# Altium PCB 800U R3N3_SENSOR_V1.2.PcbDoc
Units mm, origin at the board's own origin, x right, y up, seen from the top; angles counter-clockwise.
Board outline 152.4 x 101.6 mm, 2 copper layers (Top Layer, Bottom Layer); 17 components, 10 nets, 29 pads, 17 vias.
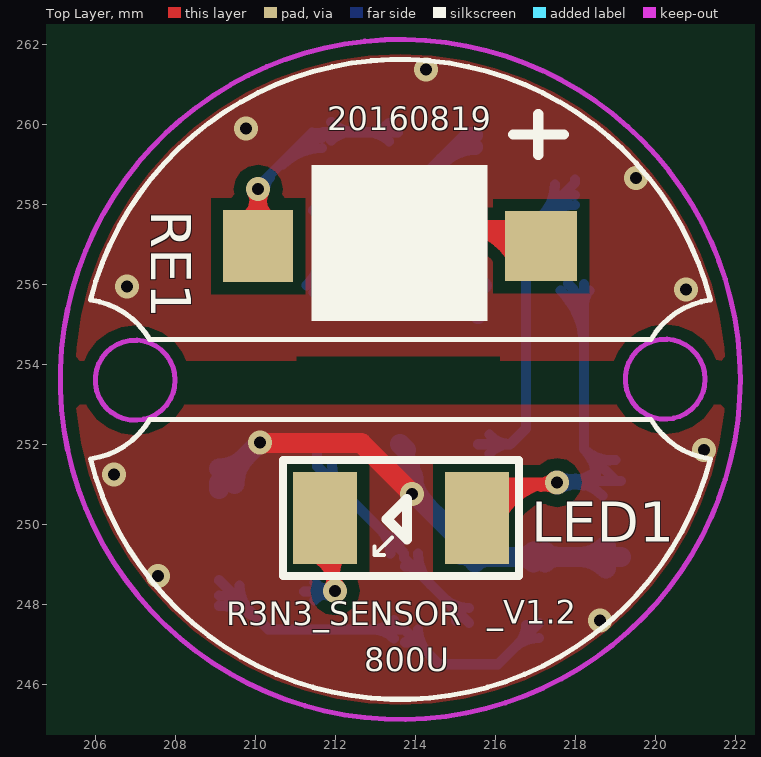
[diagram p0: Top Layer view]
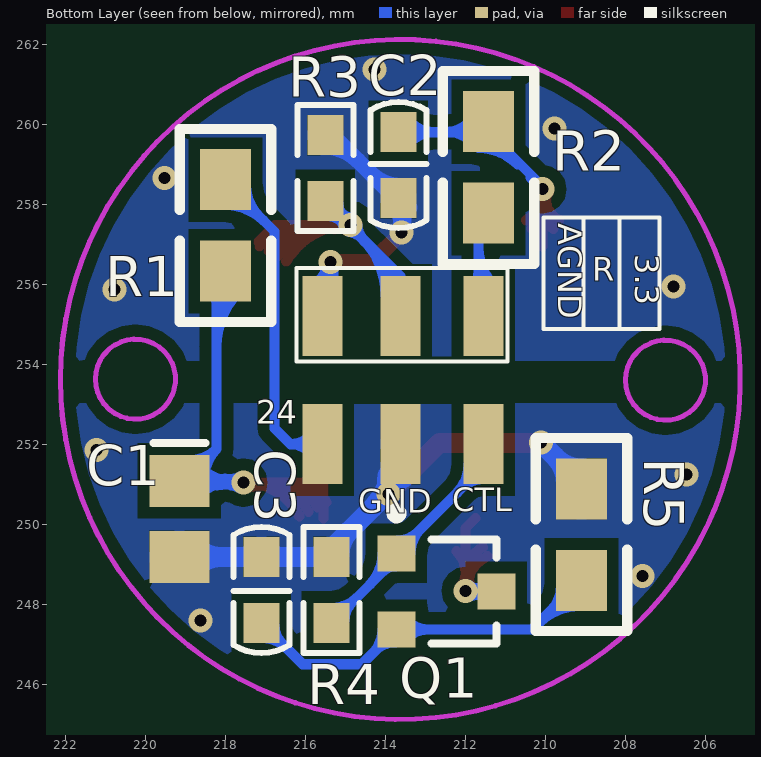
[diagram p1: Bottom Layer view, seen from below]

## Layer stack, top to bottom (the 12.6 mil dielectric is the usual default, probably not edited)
Top Layer: signal copper 0.0356
Dielectric: dielectric 0.32, FR-4, Dk 4.8
Bottom Layer: signal copper 0.0356

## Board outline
162.425,214.025 314.825,214.025 314.825,315.625 162.425,315.625

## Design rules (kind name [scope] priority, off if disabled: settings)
Clearance [All] p1: gap=0.3
PlaneConnect [Isvia] p1: planeconnectstyle=Relief reliefexpansion=0.508 reliefentries=4 reliefconductorwidth=0.254 reliefairgap=0.254
PolygonConnect [Isvia] p1: connectstyle=Direct reliefconductorwidth=0.254 reliefentries=4 polygonreliefangle="90 Angle" airgapwidth=0.254
RoutingVias [All] p1: holewidth=0.3 width=0.6 viastyle="Through Hole" minholewidth=0.3 minwidth=0.6 maxholewidth=0.3 maxwidth=0.6
SilkToSolderMaskClearance SilkscreenOverComponentPads [IsPad] p1: minsilkscreentomaskgap=0.254 clearancetoexposedcopper=TRUE
SolderMaskExpansion [All] p1: expansion=0.102
Width [All] p1: maxlimit=0.6 minlimit=0.254 preferedwidth=0.254 minimp=50.000000 maximp=50.000000 favimp=50.000000
26 further rules are at their usual default settings.

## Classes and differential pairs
component class "800U R3N3_TR": 3.3 24 C1 C2 C3 CTL GND LED1 Q1 R R1 R2 R3 R4 R5 RE1

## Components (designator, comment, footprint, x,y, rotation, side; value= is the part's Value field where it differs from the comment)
3.3 "" HOLE_SMD 211.55,255.21 r180 bottom (schematic designator 2)
24 "" HOLE_SMD 215.575,252 r180 bottom (schematic designator 1)
AGND "" HOLE_SMD 215.575,255.21 r180 bottom (schematic designator LEDCTL1)
C1 "105" C0805 219.15,250.13 r270 bottom
C2 "105" C0603 213.675,259.8 r270 bottom
C3 "102" C0603 217.1,247.53 r90 bottom
CTL "" HOLE_SMD 211.55,252 r180 bottom (schematic designator LEDCTL1)
GND "" HOLE_SMD 213.625,252 r180 bottom (schematic designator GND1)
LED1 "SIR67-21C" LED-3.5X2.8 213.65,250.15 r180 top locked
Q1 "MMBT5551" SOT-23 212.475,248.32 r270 bottom
R "" HOLE_SMD 213.625,255.21 r180 bottom (schematic designator LED_R1)
R1 "100" R0805 218,257.47 r90 bottom
R2 "100" R0805 211.425,258.92 r270 bottom
R3 "10K" R0603 215.5,259.725 r270 bottom
R4 "10K" R0603 215.35,249.18 r270 bottom
R5 "15" R0805 209.1,249.74 r270 bottom
RE1 "PD70-01C" LED9*4 213.65,256.95 r90 top locked

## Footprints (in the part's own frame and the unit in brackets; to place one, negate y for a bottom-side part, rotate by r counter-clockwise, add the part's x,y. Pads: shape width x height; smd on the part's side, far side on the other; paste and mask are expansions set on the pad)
C0603 [mm]
  rect 1x0.9 smd: 1(0,0) 2(1.65,0)
  silkscreen extent -0.75,-0.7 2.4,0.7
C0805 [mm] "Chip Capacitor; Body 2.0 x"
  rect 1.3x1.5 smd: 1(-0.95,0) 2(0.95,0)
  silkscreen extent -1.9,-0.65 -1.9,0.65
HOLE_SMD [mm]
  rect 1x2 smd: 1(0,0)
LED9*4 [mm]
  rect 1.75x1.8 smd: 1(0,-3.5)
  rect 1.8x1.75 smd: 2(0,3.575)
  silkscreen extent -1.87,-4.06 3.3,2.24
LED-3.5X2.8 [mm]
  rect 1.6x2.3 smd: 1(-1.9,0) 2(1.9,0)
  silkscreen extent -2.95,-1.45 2.95,1.45
R0603 [mm]
  rect 1x0.9 smd: 1(0,0) 2(1.65,0)
  silkscreen extent -0.75,-0.7 2.4,0.7
R0805 [mil]
  rect 60x50 smd: 1(-45,0) 2(45,0)
  silkscreen extent -95,-45 95,45
SOT-23 [mm] "SOT-23; 3 Leads; Body 3.0 x 2.6 mm"
  rect 0.9x0.95 smd: 1(-0.95,-1.25) 2(0.95,-1.25) 3(0,1.25)
  silkscreen extent -2.07,-1.38 1.3,1.25

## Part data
3.3 24 AGND CTL GND R: library part 焊
C1: library part Cap, "贴片电容"
C2 C3: library part Cap, "贴"
LED1: library part LED0, "贴"
Q1: library part NPN, "贴片NPN三极管"
R1 R2 R3 R4 R5: library part "Res Semi", "贴"
RE1: library part "Photo Sen", "贴"

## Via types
v1: diameter 0.6, hole 0.3, Top Layer to Bottom Layer, 17 vias

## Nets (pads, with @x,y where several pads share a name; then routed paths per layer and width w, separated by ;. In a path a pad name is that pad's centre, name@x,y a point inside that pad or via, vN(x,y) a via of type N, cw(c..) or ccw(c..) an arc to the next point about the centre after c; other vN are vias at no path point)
3.3V: 3.3.1 R2.2 | length 6
  Bottom Layer w0.254: 3.3.1@211.286,255.974 ccw(c210.348,256.912) 211.675,256.912 ; R2.2@211.447,257.847 cw(c210.895,257.295) 211.675,257.295 cw(c212.455,257.295) R2.2@211.903,257.847 ; 3.3.1@211.466,255.794 ccw(c210.961,256.299) 211.675,256.299 ; 211.675,256.309 ccw(c212.149,256.309) 3.3.1@211.814,255.974 ; R2.2@211.675,258.125 211.675,255.575 3.3.1@211.875,255.375
+24V: 24.1 R1.2 | length 11.8
  Bottom Layer w0.254: 24.1 216.375,252 ; 24.1@215.861,251.76 cw(c216.375,251.329) 216.375,252 ; 24.1@215.861,252.24 ccw(c216.375,252.671) 216.375,252 ; 217.041,257.581 cw(c218,256.621) R1.2@218,257.978 ; 217.171,257.711 ccw(c216.396,258.486) R1.2@217.492,258.486 ; R1.2@217.474,258.014 cw(c218,257.488) R1.2@218,258.232 ; R1.2 218,258.54 216.775,257.315 216.775,252.4 216.375,252
AGND: AGND.1 C2.2 R3.1 | length 11.4
  Top Layer w0.4: v1(213.6,257.29) 214.33,256.56 v1(215.375,256.56)
  Bottom Layer w0.4: C2.2@213.398,257.923 cw(c212.971,257.496) 213.575,257.496 cw(c214.179,257.496) C2.2@213.752,257.923 ; v1@213.513,257.34 ccw(c213.218,257.511) 213.548,257.599 ; 213.575,257.592 ccw(c213.902,257.592) v1@213.671,257.361 ; C2.2@213.575,258.15 C2.2@213.575,257.975 ; C2.2@213.575,258.45 ccw(c213.575,259.597) 214.386,258.786 ; v1(213.6,257.29) 213.575,257.315 C2.2@213.575,257.975 ; C2.2@213.621,257.668 ccw(c213.985,257.571) v1@213.681,257.349 ; 214.689,259.089 cw(c215.5,258.278) R3.1@215.5,259.425 ; R3.1 215.325,259.725 C2.2@213.575,257.975 ; AGND.1 215.375,255.41 v1(215.375,256.56) ccw(c216.047,256.56) AGND.1@215.721,255.972
  other v1: 220.775,255.87 206.8,255.94 219.525,258.65 209.775,259.89 214.275,261.37
GND: C1.2 C3.2 GND.1 R4.1 R5.1 | length 20.9
  Top Layer w0.5: v1@210.105,252.03 212.655,252.03 v1(213.925,250.76)
  Bottom Layer w0.5: R5.1 209.1,251.025 v1(210.115,252.04) ; R5.1@209.1,251.395 ccw(c209.1,252.288) 209.732,251.657 ; R5.1@209.485,251.01 cw(c210.451,251.01) 209.768,251.693 ; GND.1 GND.1@213.775,251.85 ; GND.1@213.7,251.3 213.55,251.15 213.585,251.15 215.35,249.385 R4.1 C3.2 C1.2 ; GND.1@213.875,251.5 ccw(c215.42,251.5) 214.328,250.407 ; v1@213.882,250.786 ccw(c213.398,251.077) GND.1@213.946,251.213 ; v1@213.918,250.711 cw(c213.842,250.206) 214.252,250.509 ; 214.899,249.836 cw(c214.293,249.23) R4.1@215.15,249.23 ; R4.1@215.491,249.039 cw(c215.833,248.697) 215.833,249.18 cw(c215.833,249.663) R4.1@215.491,249.321 ; C3.2@216.959,249.039 ccw(c216.617,248.697) 216.617,249.18 ccw(c216.617,249.663) C3.2@216.959,249.321 ; C3.2@217.241,249.039 cw(c217.583,248.697) 217.583,249.18 cw(c217.583,249.663) C3.2@217.241,249.321 ; C1.2@218.767,248.897 ccw(c218.084,248.214) 218.084,249.18 ccw(c218.084,250.146) C1.2@218.767,249.463
  other v1: 218.625,247.59 207.575,248.7 206.475,251.24 221.225,251.85
LEDCTL: CTL.1 Q1.1 R4.2 | length 11.1
  Bottom Layer w0.254: CTL.1@211.55,251.127 cw(c211.55,250.359) 212.093,250.902 ; CTL.1 211.55,251.445 Q1.1 213.725,249.155 R4.2 ; CTL.1@211.923,251.5 ccw(c212.956,251.5) 212.226,250.769 ; 213.131,249.864 cw(c212.537,249.27) Q1.1@213.377,249.27 ; 213.191,249.804 ccw(c213.7,250.312) Q1.1@213.7,249.593 ; Q1.1@213.75,248.947 cw(c213.75,248.505) 214.062,248.818 ; Q1.1@214.073,249.27 ccw(c215.191,249.27) 214.4,248.48 ; 214.713,248.167 ccw(c215.35,248.803) R4.2@215.35,247.903 ; 214.834,248.046 cw(c214.368,247.58) R4.2@215.027,247.58
NetC1_1: C1.1 LED1.1 R1.1 | length 25.2
  Top Layer w0.254: LED1.1@215.471,250.541 cw(c216.294,250.113) LED1.1@216.294,251.04 ; LED1.1 215.55,250.95 215.64,251.04 v1(217.55,251.04) ccw(c217.55,249.458) LED1.1@216.147,250.189 ; LED1.1@215.696,250.424 cw(c216.712,249.894) 216.712,251.04 ; LED1.1@215.922,250.306 cw(c217.131,249.676) 217.131,251.04 ; v1@217.4,251.127 cw(c217.039,251.335) 217.147,250.932 cw(c217.255,250.528) v1@217.463,250.89 ; v1@217.428,250.918 ccw(c217.132,250.622) 217.132,251.04 ccw(c217.132,251.458) v1@217.428,251.162
  Bottom Layer w0.254: v1(217.55,251.04) 217.59,251.08 C1.1 219.025,251.08 218.225,251.88 ; v1@217.636,250.89 cw(c218.016,250.233) 218.213,250.966 ; v1@217.636,251.19 ccw(c217.884,251.619) 218.012,251.14 ; R1.1@217.641,255.841 cw(c216.23,254.43) 218.225,254.43 ; v1@217.672,250.918 cw(c218.064,250.526) 218.064,251.08 ; v1@217.672,251.162 ccw(c217.871,251.361) 217.871,251.08 ; v1@217.7,250.954 cw(c217.994,250.784) 217.906,251.112 ; R1.1@217.82,256.02 cw(c216.844,255.044) 218.225,255.044 ; 218.225,255.517 cw(c218.683,255.517) R1.1@218.359,255.841 ; R1.1@218.225,256.007 218.225,251.88 ; C1.1@218.527,251.103 ccw(c217.493,251.147) 218.225,251.88 ; C1.1@218.68,250.71 ccw(c217.787,249.817) 217.787,251.08 ccw(c217.787,252.343) C1.1@218.68,251.45 ; C1.1@219.001,251.601 cw(c218.91,252.565) 218.225,251.88
NetC2_1: C2.1 R2.1 RE1.2 | length 15.3
  Top Layer w0.254: RE1.2@209.659,257.597 ccw(c209.139,258.375) v1(210.075,258.375) ; RE1.2@209.8,257.386 ccw(c209.457,257.9) 210.075,257.9 ccw(c210.693,257.9) RE1.2@210.35,257.386 ; v1@209.925,258.288 cw(c209.563,258.08) 209.967,257.972 cw(c210.37,257.864) v1@210.162,258.225 ; v1@209.953,258.253 cw(c209.657,257.957) 210.075,257.957 cw(c210.493,257.957) v1@210.197,258.253 ; v1@209.988,258.225 cw(c209.78,257.864) 210.183,257.972 cw(c210.587,258.08) v1@210.225,258.288 ; RE1.2 v1(210.075,258.375) ; RE1.2@210.491,257.597 cw(c211.011,258.375) v1(210.075,258.375)
  Bottom Layer w0.254: v1@210.025,258.39 R2.1@211.425,259.79 ; v1@210.075,258.548 ccw(c210.075,258.966) 210.37,258.67 ccw(c210.666,258.375) v1@210.248,258.375 ; 210.697,258.997 cw(c211.675,258.019) R2.1@211.675,259.402 ; R2.1@211.13,259.43 cw(c211.675,258.886) R2.1@211.675,259.656 ; R2.1@211.475,259.775 211.675,259.775 211.7,259.8 C2.1@213.575,259.8 ; R2.1@211.903,259.597 cw(c212.394,259.106) 212.394,259.8 ; R2.1@211.903,260.053 ccw(c212.515,260.665) 212.515,259.8 ; C2.1@213.347,259.572 ccw(c212.795,259.02) 212.795,259.8 ccw(c212.795,260.58) C2.1@213.347,260.028
NetC3_1: C3.1 Q1.2 R5.2 | length 15.6
  Bottom Layer w0.254: R5.2@209.1,247.962 cw(c209.1,246.429) 210.184,247.513 ; R5.2@209.1,248.216 cw(c209.1,247.296) 209.75,247.947 ; R5.2 210.327,247.37 Q1.2 214.595,246.5 216.07,246.5 C3.1 ; R5.2@209.608,248.47 ccw(c210.528,248.47) 209.877,247.82 ; Q1.2@213.472,247.142 ccw(c212.92,246.59) 212.92,247.37 ccw(c212.92,248.15) Q1.2@213.472,247.598 ; Q1.2@213.75,247.047 cw(c213.75,246.328) 214.259,246.836 ; Q1.2@214.073,247.37 ccw(c214.913,247.37) 214.319,246.776 ; 216.463,246.893 cw(c217.1,246.257) C3.1@217.1,247.157 ; 216.584,247.014 ccw(c216.118,247.48) C3.1@216.777,247.48
NetLED1_2: LED1.2 Q1.3 | length 9.5
  Top Layer w0.254: LED1.2@211.45,249.198 cw(c211.007,248.309) v1@212,248.309 ; LED1.2@211.563,249.425 cw(c211.212,248.719) 212,248.719 ; LED1.2 212,249.9 v1(212,248.33) ; v1@211.85,248.417 ccw(c211.505,248.616) 211.89,248.719 ; v1@211.878,248.452 ccw(c211.582,248.748) 212,248.748 ccw(c212.418,248.748) v1@212.122,248.452 ; 211.883,248.745 ccw(c212.305,248.858) v1@212.086,248.48 ; 212,248.779 cw(c212.771,248.779) LED1.2@212.226,249.324
  Bottom Layer w0.254: Q1.3 v1@212,248.32 ; Q1.3@211.485,248.098 cw(c212,247.611) v1@212,248.32 ; Q1.3@211.485,248.542 ccw(c212,249.029) v1@212,248.32 ; Q1.3@211.558,248.32 ccw(c211.558,248.772) v1@211.878,248.452 ; Q1.3@211.606,248.32 cw(c211.606,247.936) v1@211.878,248.208 ; v1@211.843,248.258 ccw(c211.589,248.141) 211.662,248.411 ccw(c211.726,248.652) v1@211.888,248.462 ; v1@211.842,248.401 cw(c211.545,248.537) 211.629,248.221 cw(c211.724,247.867) v1@211.911,248.181 ; v1(212,248.33) v1@212,248.32
NetLED_R1_1: R3.2 R.1 RE1.1 | length 21.3
  Top Layer w0.254: v1@214.962,257.33 cw(c215.17,256.968) 215.278,257.372 cw(c215.386,257.775) v1@215.025,257.567 ; v1@214.997,257.358 cw(c215.293,257.062) 215.293,257.48 cw(c215.293,257.898) v1@214.997,257.602 ; 215.322,257.48 cw(c215.322,255.875) RE1.1@216.701,256.697 ; 215.769,257.48 cw(c215.769,256.142) RE1.1@216.919,256.827 ; 216.217,257.48 cw(c216.217,256.408) RE1.1@217.137,256.957 ; RE1.1@216.483,256.567 ccw(c214.875,255.609) v1(214.875,257.48) 216.755,257.48 RE1.1@217.175,257.06 ; RE1.1@216.925,257.175 RE1.1
  Bottom Layer w0.254: R.1@213.49,255.71 cw(c214.347,255.71) 213.741,256.316 ; R.1@213.625,255.375 213.625,256.2 R3.2 R3.2@215.595,258.17 ; R.1@213.744,255.71 cw(c215.214,255.71) 214.175,256.75 ; R.1@213.998,255.71 cw(c216.081,255.71) 214.608,257.183 ; 214.524,257.061 cw(c215.017,256.723) v1@214.907,257.31 ; 214.558,257.133 ccw(c214.212,257.48) v1@214.702,257.48 ; 214.631,257.206 cw(c214.875,256.962) v1@214.875,257.307 ; v1@214.843,257.65 ccw(c214.755,258.122) R3.2@215.17,257.882 ; v1@214.863,257.438 cw(c215.5,256.802) R3.2@215.5,257.702 ; v1@214.875,257.653 ccw(c214.875,258.143) R3.2@215.222,257.797 ; v1@214.94,257.64 ccw(c215.073,257.972) R3.2@215.252,257.663 ; v1@214.984,257.559 ccw(c214.518,258.025) R3.2@215.177,258.025 ; v1@215.042,257.435 cw(c215.346,257.354) R3.2@215.189,257.626 ; v1@215.048,257.48 cw(c215.393,257.48) R3.2@215.149,257.724

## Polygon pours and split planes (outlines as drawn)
GND on Top Layer "T" (solid, remove dead copper, pour order 8): 205.175,252.99 222.175,252.99 222.175,245.14 205.345,245.14 205.225,245.26 205.195,245.23 205.175,245.23
AGND on Top Layer "B" (solid, remove dead copper, pour order 2): 205.225,262.1 222.075,262.1 222.075,254.215 222.2,254.09 205.225,254.09
GND on Bottom Layer "B" (solid, remove dead copper, pour order 6): 205,253.02 222.525,253.02 222.525,245.045 222.5,245.02 205.065,245.02 205.025,244.98
AGND on Bottom Layer "B" (solid, remove dead copper, pour order 4): 205.125,262.1 222.05,262.1 222.05,254.09 205.1,254.09 205.15,254.14 205.15,262.08

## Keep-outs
Keep-Out Layer:
  circle w0.127: c213.629,253.619 r8.5
  circle w0.127: c220.25,253.625 r1
  circle w0.127: c207,253.6 r1

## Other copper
Top Layer:
  pour cut-out: 211.025,254.2 216.125,254.2 216.125,253 211.025,253
Bottom Layer:
  pour cut-out: 214.3,256.24 216.31,256.24 216.34,256.21 216.34,254.18 214.285,254.18 214.275,254.17
  pour cut-out: 211.025,254.2 216.125,254.2 216.125,253 211.025,253

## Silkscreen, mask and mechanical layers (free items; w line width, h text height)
Top Overlay:
  lines w0.127: 205.879,251.635 ccw(c213.629,253.619) 221.379,251.635 cw(c221.629,253.619) 219.896,252.621 207.362,252.621 cw(c205.629,253.619) 205.879,251.635 ; 205.879,255.603 cw(c213.629,253.619) 221.379,255.603 ccw(c221.629,253.619) 219.896,254.617 207.362,254.617 ccw(c205.629,253.619) 205.879,255.603
  text "20160819" at 211.8,259.65 h1
  text "_V1.2" at 215.8,247.31 h1
  text "R3N3_SENSOR" at 209.275,247.27 h1
  text "800U" at 212.725,246.12 h1
Bottom Overlay:
  lines w0.1: 208.15,254.91 208.15,257.63 ; 209.05,254.91 209.05,257.63 ; 207.15,254.88 210.05,254.88 210.05,257.67 207.15,257.67 207.15,254.88 ; 210.95,254.07 216.225,254.07 216.225,256.4 210.95,256.4 210.95,254.07
Mechanical 1:
  circle w0.127: c213.629,253.619 r8.5
  circle w0.127: c220.25,253.625 r1
  circle w0.127: c207,253.6 r1
  lines w0.2: 211.025,253 211.025,254.2 216.125,254.2 216.125,253 211.025,253
Mechanical 3:
  lines w0.1: 205.1,253.6 222.129,253.6
  lines w0.127: 209.898,259.72 217.398,259.72 ; 209.987,259.723 ccw(c209.987,259.134) 209.398,259.134 209.398,254.72 ccw(c209.898,254.72) 209.898,254.22 217.398,254.22 ccw(c217.398,254.72) 217.898,254.72 217.898,259.22 ; 217.309,259.727 cw(c217.309,259.138) 217.898,259.138 ; 209.398,247.92 ccw(c209.898,247.92) 209.898,247.42 217.398,247.42 ccw(c217.398,247.92) 217.898,247.92 217.898,252.42 ccw(c217.398,252.42) 217.398,252.92 209.898,252.92 ccw(c209.898,252.42) 209.398,252.42 209.398,247.92
  lines w0.2: 213.625,245.45 213.625,261.5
